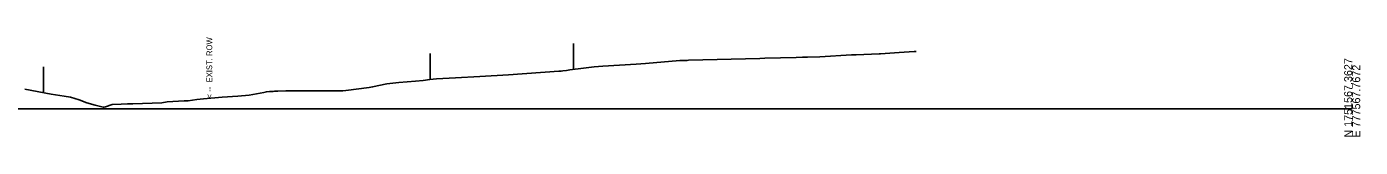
# Model space of a CAD drawing. Extents: x 776426 to 854588, y 1736205 to 1756790.
# Drawn here: x 806406.9 to 806873.6, y 1745705.1 to 1745739.7 of the extents above; entities that cross this region are included whole.
import ezdxf

# ---------------------------------------------------------------- set-up
doc = ezdxf.new("R2010")
doc.units = 0
for name, color, linetype in [('63', 7, 'Continuous'), ('DTM CONTOURS_MAJOR_TX', 7, 'Continuous'), ('DTM_X_FLOW_ARROWS', 7, 'Continuous'), ('TRANS_UNPAVED_SHOULDERS', 7, 'Continuous'), ('XS_X_ROW', 7, 'Continuous')]:
    doc.layers.add(name, color=color, linetype=linetype)

msp = doc.modelspace()

# ---------------------------------------------------------------- linework, layer by layer
at = {"layer": '63'}
msp.add_line((806412.79, 1745729.4), (806412.79, 1745720.4), dxfattribs=at)
msp.add_line((806412.79, 1745729.4), (806412.79, 1745720.4), dxfattribs=at)
at = {"layer": 'DTM CONTOURS_MAJOR_TX'}
msp.add_line((806370.79, 1745714.76), (806870.79, 1745714.76), dxfattribs=at)
at = {"layer": 'DTM_X_FLOW_ARROWS'}
msp.add_lwpolyline([(806406.16, 1745721.63), (806415.43, 1745719.91), (806419.99, 1745719.22), (806422.16, 1745718.89), (806425.27, 1745717.87), (806427.87, 1745716.89), (806430.8, 1745716.11), (806433.64, 1745715.39), (806433.96, 1745715.33), (806434.45, 1745715.48), (806436.77, 1745716.24), (806439.88, 1745716.37), (806442.18, 1745716.52), (806443.97, 1745716.57), (806454.13, 1745716.87), (806456.07, 1745717.19), (806461.93, 1745717.56), (806463.32, 1745717.59), (806466.42, 1745718.01), (806468.74, 1745718.22), (806475.25, 1745718.82), (806480.81, 1745719.24), (806484.76, 1745719.6), (806489.83, 1745720.51), (806490.78, 1745720.73), (806491.85, 1745720.81), (806493.12, 1745720.87), (806493.62, 1745720.89), (806494.73, 1745720.96), (806497.52, 1745721.07), (806502.58, 1745721.1), (806512.81, 1745721.03), (806516.87, 1745721.05), (806517.5, 1745721.05), (806518.56, 1745721.17), (806526.67, 1745722.23), (806527.94, 1745722.45), (806532.92, 1745723.55), (806537.09, 1745723.91), (806542.99, 1745724.46), (806545.61, 1745724.7), (806548.01, 1745725.01), (806550.35, 1745725.19), (806556.96, 1745725.57), (806565.43, 1745726.08), (806575.49, 1745726.68), (806593.08, 1745727.9), (806593.93, 1745727.94), (806594.54, 1745728.04), (806595.75, 1745728.2), (806596.99, 1745728.36), (806601.71, 1745728.95), (806605.52, 1745729.44), (806608.53, 1745729.61), (806620.14, 1745730.33), (806623.48, 1745730.64), (806635.51, 1745731.58), (806636.43, 1745731.63), (806636.97, 1745731.66), (806637.98, 1745731.68), (806638.51, 1745731.7), (806663.44, 1745732.38), (806665.22, 1745732.4), (806676.22, 1745732.69), (806678.41, 1745732.78), (806680.17, 1745732.77), (806684.43, 1745732.92), (806695.53, 1745733.57), (806697.12, 1745733.61), (806705.2, 1745733.91), (806705.69, 1745733.92), (806712.28, 1745734.41), (806715.76, 1745734.66), (806717.48, 1745734.74), (806718.15, 1745734.77)], dxfattribs=at)
at = {"layer": 'TRANS_UNPAVED_SHOULDERS'}
for p, q in [((806548.11, 1745734.02), (806548.11, 1745725.02)), ((806548.11, 1745734.02), (806548.11, 1745725.02)), ((806598.3, 1745737.53), (806598.3, 1745728.53)), ((806598.3, 1745737.53), (806598.3, 1745728.53))]:
    msp.add_line(p, q, dxfattribs=at)

# ---------------------------------------------------------------- texts
at = {"layer": 'DTM CONTOURS_MAJOR_TX'}
for s, p in [('N 1751567.3627', (806870.79, 1745704.76)), ('E 777567.7672', (806873.59, 1745704.76))]:
    msp.add_text(s, height=2.8, rotation=90, dxfattribs=at).set_placement(p)
at = {"layer": 'XS_X_ROW'}
msp.add_text('< --  EXIST. ROW', height=2, rotation=90, dxfattribs=at).set_placement((806471.79, 1745718.41))

doc.saveas('drawing.dxf')
